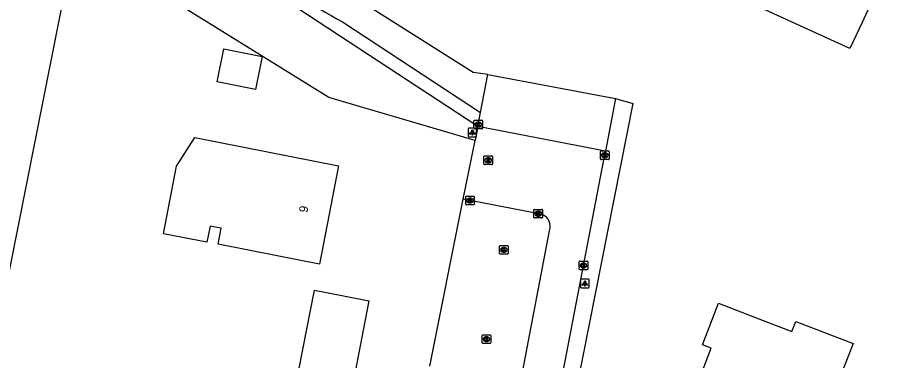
# Model space of a CAD drawing. Extents: x 162417 to 163721, y 384268 to 385416.
# Drawn here: x 163118.6 to 163218.5, y 385291.7 to 385331.4 of the extents above; entities that cross this region are included whole.
import ezdxf

# ---------------------------------------------------------------- set-up
doc = ezdxf.new("R2010")
doc.units = 0
for name, color, linetype in [('IMGEO_Gemengd_bos', 7, 'Continuous'), ('IMGEO_Groenvoorziening', 7, 'Continuous'), ('IMGEO_Kolk', 7, 'Continuous'), ('IMGEO_Lichtpunt', 7, 'Continuous'), ('IMGEO_Loofbos', 7, 'Continuous'), ('IMGEO_Pand', 7, 'Continuous'), ('IMGEO_Pand_nummerreeks', 7, 'Continuous'), ('IMGEO_Parkeervlak_open', 7, 'Continuous'), ('IMGEO_Rijbaan_lokaal_gesloten', 7, 'Continuous'), ('IMGEO_Rioolput', 7, 'Continuous'), ('IMGEO_Voetpad_halfverhard', 7, 'Continuous')]:
    doc.layers.add(name, color=color, linetype=linetype)

msp = doc.modelspace()

# ---------------------------------------------------------------- linework, layer by layer
at = {"layer": 'IMGEO_Gemengd_bos'}
msp.add_lwpolyline([(163171.607, 385317.191), (163154.656, 385322.143), (163125.257, 385340.42), (163123.467, 385331.446), (163115.673, 385292.374)], dxfattribs=at)
at = {"layer": 'IMGEO_Groenvoorziening'}
msp.add_lwpolyline([(163187.896, 385322.052), (163189.889, 385321.464), (163182.62, 385284.847)], dxfattribs=at)
at = {"layer": 'IMGEO_Kolk'}
for p, q in [((163171.473, 385318.598), (163171.473, 385319.45)), ((163171.548, 385319.524), (163172.4, 385319.524)), ((163171.961, 385319.304), (163171.986, 385319.304)), ((163172.474, 385319.45), (163172.474, 385318.598)), ((163172.4, 385318.524), (163171.548, 385318.524)), ((163171.984, 385318.744), (163171.959, 385318.744)), ((163186.127, 385315.053), (163186.127, 385315.905)), ((163186.202, 385315.979), (163187.054, 385315.979)), ((163187.128, 385315.905), (163187.128, 385315.053)), ((163187.054, 385314.979), (163186.202, 385314.979)), ((163186.638, 385315.199), (163186.613, 385315.199)), ((163186.615, 385315.759), (163186.64, 385315.759)), ((163170.519, 385309.817), (163170.519, 385310.669)), ((163170.594, 385310.743), (163171.446, 385310.743)), ((163171.03, 385309.963), (163171.005, 385309.963)), ((163171.007, 385310.523), (163171.032, 385310.523)), ((163171.52, 385310.669), (163171.52, 385309.817)), ((163171.446, 385309.743), (163170.594, 385309.743)), ((163178.435, 385308.293), (163178.435, 385309.145)), ((163178.51, 385309.219), (163179.362, 385309.219)), ((163178.923, 385308.999), (163178.948, 385308.999)), ((163179.436, 385309.145), (163179.436, 385308.293)), ((163179.362, 385308.219), (163178.51, 385308.219)), ((163178.946, 385308.439), (163178.921, 385308.439)), ((163174.437, 385304.108), (163174.437, 385304.96)), ((163174.512, 385305.034), (163175.364, 385305.034)), ((163174.925, 385304.814), (163174.95, 385304.814)), ((163175.438, 385304.96), (163175.438, 385304.108)), ((163175.364, 385304.034), (163174.512, 385304.034)), ((163174.948, 385304.254), (163174.923, 385304.254)), ((163183.672, 385302.304), (163183.672, 385303.156)), ((163183.747, 385303.23), (163184.599, 385303.23)), ((163184.16, 385303.01), (163184.185, 385303.01)), ((163184.673, 385303.156), (163184.673, 385302.304)), ((163184.599, 385302.23), (163183.747, 385302.23)), ((163184.183, 385302.45), (163184.158, 385302.45)), ((163172.432, 385293.77), (163172.432, 385294.622)), ((163172.507, 385294.696), (163173.359, 385294.696)), ((163172.943, 385293.916), (163172.918, 385293.916)), ((163172.92, 385294.476), (163172.945, 385294.476)), ((163173.433, 385294.622), (163173.433, 385293.77)), ((163173.359, 385293.696), (163172.507, 385293.696))]:
    msp.add_line(p, q, dxfattribs=at)
for points in [[(163171.473, 385318.598), (163171.473, 385319.45)], [(163171.548, 385319.524), (163172.4, 385319.524)], [(163171.794, 385319.224), (163171.917, 385319.224), (163171.917, 385319.073), (163172.047, 385319.224), (163172.211, 385319.224), (163172.065, 385319.073), (163172.218, 385318.824), (163172.066, 385318.824), (163171.981, 385318.988), (163171.917, 385318.921), (163171.917, 385318.824), (163171.794, 385318.824), (163171.794, 385319.224)], [(163172.474, 385319.45), (163172.474, 385318.598)], [(163172.4, 385318.524), (163171.548, 385318.524)], [(163186.127, 385315.053), (163186.127, 385315.905)], [(163186.202, 385315.979), (163187.054, 385315.979)], [(163187.128, 385315.905), (163187.128, 385315.053)], [(163187.054, 385314.979), (163186.202, 385314.979)], [(163186.448, 385315.679), (163186.571, 385315.679), (163186.571, 385315.528), (163186.701, 385315.679), (163186.865, 385315.679), (163186.719, 385315.528), (163186.872, 385315.279), (163186.72, 385315.279), (163186.635, 385315.443), (163186.571, 385315.376), (163186.571, 385315.279), (163186.448, 385315.279), (163186.448, 385315.679)], [(163170.519, 385309.817), (163170.519, 385310.669)], [(163170.594, 385310.743), (163171.446, 385310.743)], [(163170.84, 385310.443), (163170.963, 385310.443), (163170.963, 385310.292), (163171.093, 385310.443), (163171.257, 385310.443), (163171.111, 385310.292), (163171.264, 385310.043), (163171.112, 385310.043), (163171.027, 385310.207), (163170.963, 385310.14), (163170.963, 385310.043), (163170.84, 385310.043), (163170.84, 385310.443)], [(163171.52, 385310.669), (163171.52, 385309.817)], [(163171.446, 385309.743), (163170.594, 385309.743)], [(163178.435, 385308.293), (163178.435, 385309.145)], [(163178.51, 385309.219), (163179.362, 385309.219)], [(163178.756, 385308.919), (163178.879, 385308.919), (163178.879, 385308.768), (163179.009, 385308.919), (163179.173, 385308.919), (163179.027, 385308.768), (163179.18, 385308.519), (163179.028, 385308.519), (163178.943, 385308.683), (163178.879, 385308.616), (163178.879, 385308.519), (163178.756, 385308.519), (163178.756, 385308.919)], [(163179.436, 385309.145), (163179.436, 385308.293)], [(163179.362, 385308.219), (163178.51, 385308.219)], [(163174.437, 385304.108), (163174.437, 385304.96)], [(163174.512, 385305.034), (163175.364, 385305.034)], [(163175.438, 385304.96), (163175.438, 385304.108)], [(163175.364, 385304.034), (163174.512, 385304.034)], [(163174.758, 385304.734), (163174.881, 385304.734), (163174.881, 385304.583), (163175.011, 385304.734), (163175.175, 385304.734), (163175.029, 385304.583), (163175.182, 385304.334), (163175.03, 385304.334), (163174.945, 385304.498), (163174.881, 385304.431), (163174.881, 385304.334), (163174.758, 385304.334), (163174.758, 385304.734)], [(163183.672, 385302.304), (163183.672, 385303.156)], [(163183.747, 385303.23), (163184.599, 385303.23)], [(163183.993, 385302.93), (163184.116, 385302.93), (163184.116, 385302.779), (163184.246, 385302.93), (163184.41, 385302.93), (163184.264, 385302.779), (163184.417, 385302.53), (163184.265, 385302.53), (163184.18, 385302.694), (163184.116, 385302.627), (163184.116, 385302.53), (163183.993, 385302.53), (163183.993, 385302.93)], [(163184.673, 385303.156), (163184.673, 385302.304)], [(163184.599, 385302.23), (163183.747, 385302.23)], [(163172.432, 385293.77), (163172.432, 385294.622)], [(163172.507, 385294.696), (163173.359, 385294.696)], [(163172.753, 385294.396), (163172.876, 385294.396), (163172.876, 385294.245), (163173.006, 385294.396), (163173.17, 385294.396), (163173.024, 385294.245), (163173.177, 385293.996), (163173.025, 385293.996), (163172.94, 385294.16), (163172.876, 385294.093), (163172.876, 385293.996), (163172.753, 385293.996), (163172.753, 385294.396)], [(163173.433, 385294.622), (163173.433, 385293.77)], [(163173.359, 385293.696), (163172.507, 385293.696)]]:
    msp.add_lwpolyline(points, dxfattribs=at)
for centre, start, end in [((163171.55, 385319.448), 91.55205, 178.44795), ((163171.55, 385319.448), 91.55205, 178.44795), ((163172.398, 385319.448), 1.55205, 88.44795), ((163172.398, 385319.448), 1.55205, 88.44795), ((163171.55, 385318.6), 181.55205, 268.44795), ((163171.55, 385318.6), 181.55205, 268.44795), ((163172.398, 385318.6), 271.55205, 358.44795), ((163172.398, 385318.6), 271.55205, 358.44795), ((163186.204, 385315.903), 91.55205, 178.44795), ((163186.204, 385315.903), 91.55205, 178.44795), ((163187.052, 385315.903), 1.55205, 88.44795), ((163187.052, 385315.903), 1.55205, 88.44795), ((163186.204, 385315.055), 181.55205, 268.44795), ((163186.204, 385315.055), 181.55205, 268.44795), ((163187.052, 385315.055), 271.55205, 358.44795), ((163187.052, 385315.055), 271.55205, 358.44795), ((163170.596, 385310.667), 91.55205, 178.44795), ((163170.596, 385310.667), 91.55205, 178.44795), ((163170.596, 385309.819), 181.55205, 268.44795), ((163170.596, 385309.819), 181.55205, 268.44795), ((163171.444, 385310.667), 1.55205, 88.44795), ((163171.444, 385310.667), 1.55205, 88.44795), ((163171.444, 385309.819), 271.55205, 358.44795), ((163171.444, 385309.819), 271.55205, 358.44795), ((163178.512, 385309.143), 91.55205, 178.44795), ((163178.512, 385309.143), 91.55205, 178.44795), ((163179.36, 385309.143), 1.55205, 88.44795), ((163179.36, 385309.143), 1.55205, 88.44795), ((163178.512, 385308.295), 181.55205, 268.44795), ((163178.512, 385308.295), 181.55205, 268.44795), ((163179.36, 385308.295), 271.55205, 358.44795), ((163179.36, 385308.295), 271.55205, 358.44795), ((163174.514, 385304.958), 91.55205, 178.44795), ((163174.514, 385304.958), 91.55205, 178.44795), ((163175.362, 385304.958), 1.55205, 88.44795), ((163175.362, 385304.958), 1.55205, 88.44795), ((163174.514, 385304.11), 181.55205, 268.44795), ((163174.514, 385304.11), 181.55205, 268.44795), ((163175.362, 385304.11), 271.55205, 358.44795), ((163175.362, 385304.11), 271.55205, 358.44795), ((163183.749, 385303.154), 91.55205, 178.44795), ((163183.749, 385303.154), 91.55205, 178.44795), ((163184.597, 385303.154), 1.55205, 88.44795), ((163184.597, 385303.154), 1.55205, 88.44795), ((163183.749, 385302.306), 181.55205, 268.44795), ((163183.749, 385302.306), 181.55205, 268.44795), ((163184.597, 385302.306), 271.55205, 358.44795), ((163184.597, 385302.306), 271.55205, 358.44795), ((163172.509, 385294.62), 91.55205, 178.44795), ((163172.509, 385294.62), 91.55205, 178.44795), ((163173.357, 385294.62), 1.55205, 88.44795), ((163173.357, 385294.62), 1.55205, 88.44795), ((163172.509, 385293.772), 181.55205, 268.44795), ((163172.509, 385293.772), 181.55205, 268.44795), ((163173.357, 385293.772), 271.55205, 358.44795), ((163173.357, 385293.772), 271.55205, 358.44795)]:
    msp.add_arc(centre, 0.0765, start, end, dxfattribs=at)
for centre, major_axis, ratio, start_param, end_param in [((163171.96, 385319.024), (-0.387, 0.002), 0.722429, 4.712389, 7.853982), ((163171.985, 385319.024), (-0.39, 0.002), 0.717154, 1.570796, 4.712389), ((163186.614, 385315.479), (-0.387, 0.002), 0.722429, 4.712389, 7.853982), ((163186.639, 385315.479), (-0.39, 0.002), 0.717154, 1.570796, 4.712389), ((163171.006, 385310.243), (-0.387, 0.002), 0.722429, 4.712389, 7.853982), ((163171.031, 385310.243), (-0.39, 0.002), 0.717154, 1.570796, 4.712389), ((163178.922, 385308.719), (-0.387, 0.002), 0.722429, 4.712389, 7.853982), ((163178.947, 385308.719), (-0.39, 0.002), 0.717154, 1.570796, 4.712389), ((163174.924, 385304.534), (-0.387, 0.002), 0.722429, 4.712389, 7.853982), ((163174.949, 385304.534), (-0.39, 0.002), 0.717154, 1.570796, 4.712389), ((163184.159, 385302.73), (-0.387, 0.002), 0.722429, 4.712389, 7.853982), ((163184.184, 385302.73), (-0.39, 0.002), 0.717154, 1.570796, 4.712389), ((163172.919, 385294.196), (-0.387, 0.002), 0.722429, 4.712389, 7.853982), ((163172.944, 385294.196), (-0.39, 0.002), 0.717154, 1.570796, 4.712389)]:
    msp.add_ellipse(centre, major_axis=major_axis, ratio=ratio, start_param=start_param, end_param=end_param, dxfattribs=at)
at = {"layer": 'IMGEO_Lichtpunt'}
for p, q in [((163170.791, 385318.513), (163170.791, 385317.706)), ((163170.791, 385318.513), (163170.791, 385317.706)), ((163171.693, 385318.608), (163170.885, 385318.608)), ((163171.693, 385318.608), (163170.885, 385318.608)), ((163171.787, 385317.706), (163171.787, 385318.513)), ((163171.787, 385317.706), (163171.787, 385318.513)), ((163170.885, 385317.612), (163171.693, 385317.612)), ((163170.885, 385317.612), (163171.693, 385317.612)), ((163183.842, 385301.042), (163183.842, 385300.235)), ((163183.842, 385301.042), (163183.842, 385300.235)), ((163184.744, 385301.137), (163183.936, 385301.137)), ((163184.744, 385301.137), (163183.936, 385301.137)), ((163184.838, 385300.235), (163184.838, 385301.042)), ((163184.838, 385300.235), (163184.838, 385301.042)), ((163183.936, 385300.141), (163184.744, 385300.141)), ((163183.936, 385300.141), (163184.744, 385300.141))]:
    msp.add_line(p, q, dxfattribs=at)
for points in [[(163171.165, 385318.177), (163171.204, 385318.149), (163171.016, 385317.887), (163170.978, 385317.914), (163171.165, 385318.177)], [(163171.267, 385318.129), (163171.314, 385318.129), (163171.314, 385317.807), (163171.267, 385317.807), (163171.267, 385318.129)], [(163171.377, 385318.149), (163171.415, 385318.176), (163171.602, 385317.914), (163171.563, 385317.886), (163171.377, 385318.149)], [(163184.216, 385300.706), (163184.255, 385300.678), (163184.067, 385300.416), (163184.029, 385300.443), (163184.216, 385300.706)], [(163184.318, 385300.658), (163184.365, 385300.658), (163184.365, 385300.336), (163184.318, 385300.336), (163184.318, 385300.658)], [(163184.428, 385300.678), (163184.466, 385300.705), (163184.653, 385300.443), (163184.614, 385300.415), (163184.428, 385300.678)]]:
    msp.add_lwpolyline(points, dxfattribs=at)
for centre in [(163171.29, 385318.311), (163184.341, 385300.84)]:
    msp.add_circle(centre, 0.0994, dxfattribs=at)
for centre, start, end in [((163170.885, 385318.513), 90, 180), ((163170.885, 385318.513), 90, 180), ((163171.693, 385318.513), 0, 90), ((163171.693, 385318.513), 0, 90), ((163170.885, 385317.706), 180, 270), ((163170.885, 385317.706), 180, 270), ((163171.693, 385317.706), 270, 0), ((163171.693, 385317.706), 270, 360), ((163183.936, 385301.042), 90, 180), ((163183.936, 385301.042), 90, 180), ((163184.744, 385301.042), 0, 90), ((163184.744, 385301.042), 0, 90), ((163183.936, 385300.235), 180, 270), ((163183.936, 385300.235), 180, 270), ((163184.744, 385300.235), 270, 0), ((163184.744, 385300.235), 270, 360)]:
    msp.add_arc(centre, 0.0946, start, end, dxfattribs=at)
at = {"layer": 'IMGEO_Loofbos'}
msp.add_lwpolyline([(163173.081, 385324.811), (163171.395, 385325.065), (163149.786, 385338.705), (163158.761, 385355.27), (163167.217, 385370.454)], dxfattribs=at)
at = {"layer": 'IMGEO_Pand'}
for points in [[(163202.351, 385342.174), (163204.438, 385346.717), (163209.926, 385344.196), (163208.035, 385340.08), (163211.162, 385338.643), (163211.402, 385339.165), (163213.662, 385338.126), (163213.44, 385337.642), (163218.493, 385335.32), (163216.406, 385330.777), (163215.043, 385327.812), (163199.114, 385335.13), (163202.351, 385342.174)], [(163142.502, 385327.777), (163146.926, 385326.898), (163146.169, 385323.091), (163141.745, 385323.971), (163142.502, 385327.777)], [(163141.831, 385305.176), (163142.192, 385307.025), (163140.907, 385307.276), (163140.545, 385305.418), (163135.506, 385306.4), (163137.03, 385314.22), (163139.137, 385317.515), (163155.804, 385314.266), (163153.585, 385302.884), (163148.678, 385303.841), (163141.831, 385305.176)], [(163152.601, 385290.388), (163151.193, 385290.662), (163152.99, 385299.879), (163154.398, 385299.605), (163159.305, 385298.648), (163157.508, 385289.431), (163152.601, 385290.388)], [(163203.854, 385282.976), (163204.113, 385283.651), (163201.649, 385284.597), (163202.226, 385286.098), (163197.027, 385288.095), (163198.968, 385293.147), (163197.957, 385293.535), (163199.809, 385298.356), (163204.477, 385296.563), (163208.325, 385295.085), (163208.776, 385296.259), (163215.397, 385293.716), (163213.149, 385287.864), (163212.276, 385288.199), (163211.238, 385285.496), (163209.445, 385280.828), (163203.854, 385282.976)]]:
    msp.add_lwpolyline(points, dxfattribs=at)
at = {"layer": 'IMGEO_Parkeervlak_open'}
for points in [[(163172.237, 385320.408), (163173.081, 385324.811)], [(163173.081, 385324.811), (163187.896, 385322.052)], [(163187.896, 385322.052), (163186.724, 385315.966)], [(163166.376, 385291.066), (163170.245, 385310.39)]]:
    msp.add_lwpolyline(points, dxfattribs=at)
at = {"layer": 'IMGEO_Rijbaan_lokaal_gesloten'}
for points in [[(163171.931, 385318.811), (163171.607, 385317.191)], [(163186.724, 385315.966), (163171.931, 385318.811)], [(163170.245, 385310.39), (163171.607, 385317.191)], [(163181.472, 385288.627), (163186.724, 385315.966)], [(163179.414, 385308.626), (163170.245, 385310.39)], [(163176.675, 385288.328), (163176.814, 385288.887), (163176.828, 385288.946), (163180.236, 385306.75)]]:
    msp.add_lwpolyline(points, dxfattribs=at)
msp.add_arc((163178.846, 385307.259), 1.48, 339.87645, 67.44638, dxfattribs=at)
at = {"layer": 'IMGEO_Rioolput'}
for p, q in [((163172.632, 385314.467), (163172.632, 385315.319)), ((163172.707, 385315.393), (163173.559, 385315.393)), ((163173.12, 385315.173), (163173.145, 385315.173)), ((163173.633, 385315.319), (163173.633, 385314.467)), ((163173.559, 385314.393), (163172.707, 385314.393)), ((163173.143, 385314.613), (163173.118, 385314.613))]:
    msp.add_line(p, q, dxfattribs=at)
for points in [[(163172.632, 385314.467), (163172.632, 385315.319)], [(163172.707, 385315.393), (163173.559, 385315.393)], [(163173.221, 385315.091), (163172.969, 385315.093), (163172.969, 385314.693)], [(163172.969, 385314.693), (163173.093, 385314.693), (163173.093, 385314.855), (163173.104, 385314.855)], [(163173.147, 385315.012), (163173.093, 385315.012), (163173.093, 385314.931)], [(163173.093, 385314.931), (163173.145, 385314.931)], [(163173.151, 385314.826), (163173.222, 385314.693), (163173.362, 385314.693), (163173.297, 385314.819)], [(163173.633, 385315.319), (163173.633, 385314.467)], [(163173.559, 385314.393), (163172.707, 385314.393)]]:
    msp.add_lwpolyline(points, dxfattribs=at)
for centre, radius, start, end in [((163172.709, 385315.317), 0.0765, 91.55205, 178.44795), ((163172.709, 385315.317), 0.0765, 91.55205, 178.44795), ((163173.103, 385314.802), 0.0533, 26.02933, 88.69889), ((163173.129, 385315.12), 0.19, 274.7715, 282.96867), ((163173.153, 385314.916), 0.0964, 77.00612, 93.18647), ((163173.167, 385314.973), 0.0378, 276.66336, 79.67722), ((163173.22, 385314.981), 0.109, 350.36119, 89.41601), ((163173.218, 385314.981), 0.112, 277.58423, 350.98172), ((163173.202, 385314.766), 0.108, 29.51342, 73.79051), ((163173.557, 385315.317), 0.0765, 1.55205, 88.44795), ((163173.557, 385315.317), 0.0765, 1.55205, 88.44795), ((163172.709, 385314.469), 0.0765, 181.55205, 268.44795), ((163172.709, 385314.469), 0.0765, 181.55205, 268.44795), ((163173.557, 385314.469), 0.0765, 271.55205, 358.44795), ((163173.557, 385314.469), 0.0765, 271.55205, 358.44795)]:
    msp.add_arc(centre, radius, start, end, dxfattribs=at)
for centre, major_axis, ratio, start_param, end_param in [((163173.119, 385314.893), (-0.387, 0.002), 0.722429, 4.712389, 7.853982), ((163173.144, 385314.893), (-0.39, 0.002), 0.717154, 1.570796, 4.712389)]:
    msp.add_ellipse(centre, major_axis=major_axis, ratio=ratio, start_param=start_param, end_param=end_param, dxfattribs=at)
at = {"layer": 'IMGEO_Voetpad_halfverhard'}
for points in [[(163171.931, 385318.811), (163149.97, 385333.18)], [(163156.23, 385330.911), (163172.237, 385320.408)], [(163171.931, 385318.811), (163172.237, 385320.408)]]:
    msp.add_lwpolyline(points, dxfattribs=at)
msp.add_arc((163190.047, 385392.199), 69.998, 221.82377, 241.11148, dxfattribs=at)

# ---------------------------------------------------------------- texts
at = {"layer": 'IMGEO_Pand_nummerreeks'}
msp.add_text('9', height=1, rotation=78.96817, dxfattribs=at).set_placement((163152.168, 385308.787))

doc.saveas('drawing.dxf')
